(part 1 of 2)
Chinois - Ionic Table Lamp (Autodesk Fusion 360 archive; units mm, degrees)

design "Marble Base - Ionic Table Lamp - 120V" references "2-Pole Plug End", "Trove - TL", "Marble Base - Plastic Insert", "Balon v2", "Chinois", "Marble Base - Silicone Gasket", "Rubber Grommet", "Neoprene Pad", "T9 - Bulb", "T9-5In", "Arca Tall", "Facet Petite"
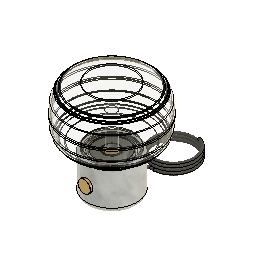
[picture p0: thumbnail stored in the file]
sketch "Sketch1" plane through (0, 0, 0) normal (0, 0, 1) x axis (1, 0, 0)
  circle C1 centre (0, 0) radius 63.5
  point P1 (0, 0)
  point P2 (0, 0)
  coincident P1 P2
extrude "Extrude1" new body sketch "Sketch1" along normal blind 101.6 bodies "Marble Base"
sketch "Sketch2" plane through (0, 0, 101.6) normal (0, 0, 1) x axis (-1, 0, 0)
  circle C1 centre (0, 0) radius 63.5
  circle C2 centre (0, 0) radius 53.975
  concentric C1 C2
  dimension "d3" diameter C2 = 107.95
extrude "Extrude2" cut sketch "Sketch2" profile of C2 against normal blind 34.925
sketch "Sketch3" plane through (0, 0, 66.675) normal (0, 0, 1) x axis (-1, 0, 0)
  circle C1 centre (0, 0) radius 53.975
  circle C2 centre (0, 0) radius 49.276
  point P1 (0, 0)
  point P3 (0, 0)
  coincident P1 P3
  dimension "d6" diameter C2 = 98.552
extrude "Extrude3" cut sketch "Sketch3" profile of C2 against normal blind 45.72
sketch "Sketch4" plane through (0, 0, 0) normal (0, 1, 0) x axis (1, 0, 0)
  circle C1 centre (0, -50.8) radius 3.81
  dimension "d9" diameter C1 = 7.62
extrude "Extrude4" cut sketch "Sketch4" against normal blind 127
sketch "Sketch5" plane through (0, 0, 0) normal (0, 1, 0) x axis (1, 0, 0)
  line L1 (0, -25.4) -> (0, 0)
  line L2 (0, -30.48) -> (0, -25.4)
  circle C1 centre (0, -30.48) radius 5.08
  point P1 (0, 0)
  point P2 (0, 0)
  point P4 (0, -30.48)
  point P5 (0, -30.48)
  coincident P1 P2
  vertical L1
  parallel L1 L2
  coincident P4 P5
  dimension "d12" diameter C1 = 10.16
extrude "Extrude5" cut sketch "Sketch5" profile of C1 along normal blind 114.3
fillet "Fillet1" radius 6.35 3.175 4.064
derived_base_feature "Derived Base Feature1" bodies "Rotary Switch"
derived_base_feature "Derived Base Feature1" bodies "Coiled - SVT (Blk Fabric)"
derived_base_feature "Derived Base Feature1" bodies "Glass Globe"
derived_base_feature "Derived Base Feature1" bodies "Metal Housing"
derived_base_feature "Derived Base Feature1" bodies "Metal Socket Cover"
derived_base_feature "Derived Base Feature1" bodies "Porcelain Socket"
derived_base_feature "Derived Base Feature1" bodies "Brass Dial - Dimmer Knob"
component_from_bodies "Body->Comp1"
offset_faces "OffsetFaces1" distance 12.7
offset_faces "OffsetFaces2" distance -12.7
derived_base_feature "Derived Base Feature1" bodies "Solitaire Petite"
move "Move1"
offset_faces "OffsetFaces1" distance 20.32
move "Move2"
extrude "Extrude6" add of existing geometry blind 25.4
offset_faces "OffsetFaces2" distance -3.81
fillet "Fillet2" radius 2.54
move "Move3"
derived_base_feature "Derived Base Feature2" bodies "Facet Petite"
move "Move4"
offset_faces "OffsetFaces1" distance 2.54
move "Move1"
derived_base_feature "Derived Base Feature1" bodies "Body1"
derived_base_feature "Derived Base Feature1" bodies "Body1"
derived_base_feature "Derived Base Feature1" bodies "Body1"
derived_base_feature "Derived Base Feature1" bodies "Body1"
derived_base_feature "Derived Base Feature1" bodies "Body1"
derived_base_feature "Derived Base Feature1" bodies "Body1", "Body2"
derived_base_feature "Derived Base Feature1" bodies "Body1"
position "Position1"
external_derived "ExternalDerived5" bodies "Plastic Insert"
derived_instance "DerivedInstance15"
offset_faces "OffsetFaces1" distance 3.81
offset_faces "OffsetFaces2" distance -1.0414
move "Move6"
external_derived "ExternalDerived6" sketch "Sketch3" bodies "Silicone Gasket"
derived_instance "DerivedInstance16"
offset_faces "OffsetFaces3" distance -10.795
move "Move1"
move_face "MoveFace1"
position "Position2"
position "Position3"
position "Position4"
position "Position5"
move "Move2"
position "Position6"
offset_faces "OffsetFaces2" distance -7.62
chamfer "Chamfer1" distance 0.381
remove_instance "RemoveInstance1"
remove_instance "RemoveInstance2"
remove_instance "RemoveInstance3"
remove_instance "RemoveInstance4"
move "Move1"
derived_base_feature "Derived Base Feature5" bodies "Oculo Petite"
align "Align1"
external_derived "ExternalDerived8"
derived_base_feature "Derived Base Feature7" bodies "Balon v2"
derived_base_feature "Derived Base Feature8" bodies "Balon v3"
align "Align3"
align "Align4"
external_derived "ExternalDerived10"
component_insert "Component Insert1"
position "Position7"
position "Position8"
derived_base_feature "Derived Base Feature11" bodies "Trove - TL"
move "Move10"
move "Move11"
remove_instance "RemoveInstance5"
split "Split1" bodies "Trove - TL (1)"
remove_body "RemoveBody2"
remove_body "RemoveBody3"
external_derived "ExternalDerived13" bodies "Trove - TL"
derived_instance "DerivedInstance20"
remove_body "RemoveBody4"
remove_body "RemoveBody5"
component_insert "Component Insert2"
component_insert "Component Insert3"
component_from_bodies "Body->Comp2"
remove_body "RemoveBody7"
move "Move12"
move "Move13"
sketch "Sketch6" plane through (0, 0, 97.917) normal (0, 0, 1) x axis (-1, 0, 0)
  circle C1 centre (0, 0) radius 41.275
  circle C2 centre (0, 0) radius 19.685
  arc A1 centre (0, 0) radius 29.3982 clockwise from (-27.6283, 10.0466) to (27.6283, 10.0466)
  arc A2 centre (0, 0) radius 26.2232 clockwise from (-24.6444, 8.9616) to (24.6444, 8.9616)
  arc A3 centre (0, 0) radius 32.5732 clockwise from (-30.6121, 11.1317) to (30.6121, 11.1317)
  arc A4 centre (0, 0) radius 35.7482 clockwise from (-33.596, 12.2167) to (33.596, 12.2167)
  point P1 (0, 0)
  point P3 (0, 0)
  coincident P1 P3
  dimension "d37" = -3.175
  dimension "d38" = 3.175
  dimension "d39" = 6.35
  dimension "d40" Text1-Height = 2.54
  dimension "d41" Text2-Height = 2.54
  dimension "d42" Text3-Height = 2.54
  dimension "d43" Text4-Height = 2.54
extrude "Extrude1" cut sketch "Sketch6" against normal blind 0.254
external_derived "ExternalDerived14" bodies "Rubber Grommet"
derived_instance "DerivedInstance19"
external_derived "ExternalDerived15" bodies "2-Pole Plug End"
derived_instance "DerivedInstance18"
external_derived "ExternalDerived16" bodies "Neoprene Pad"
derived_instance "DerivedInstance17"
position "Position9"
position "Position10"
position "Position11"
position "Position12"
external_derived "ExternalDerived17" bodies "Chinois"
derived_instance "DerivedInstance21"
position "Position13"
move "Move3"
remove_body "RemoveBody8"
component_insert "Component Insert4"
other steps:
derived_base_feature "Derived Base Feature1" bodies "Trove - TL"
derived_base_feature "Derived Base Feature1" bodies "Chinois"
derived_base_feature "Derived Base Feature1" bodies "Rubber Grommet"
derived_base_feature "Derived Base Feature1" bodies "2-Pole Plug End"
derived_base_feature "Derived Base Feature1" bodies "Neoprene Pad"
move "Move1"
base_feature "Base Feature1" bodies "Oculo Petite"
derived_base_feature "Derived Base Feature1" bodies "Plastic Insert"
derived_base_feature "Derived Base Feature1" bodies "Silicone Gasket"
base_feature "Base Feature1" bodies "Marble Base"
move "Move8"
derived_base_feature "Derived Base Feature"
create_component "CreateComponent1"
create_component "CreateComponent2"
create_component "CreateComponent3"
create_component "CreateComponent4"
create_component "CreateComponent5"
create_component "CreateComponent6"
create_component "CreateComponent7"
create_component "CreateComponent8"
remove_body "RemoveBody1"
create_component "CreateComponent9"
create_component "CreateComponent10"
create_component "CreateComponent11"
create_component "CreateComponent12"
create_component "CreateComponent13"
create_component "CreateComponent14"
create_component "CreateComponent15"
create_component "CreateComponent16"
create_component "CreateComponent17"
create_component "CreateComponent18"
remove_body "RemoveBody6"
create_component "CreateComponent19"
create_component "CreateComponent20"
create_component "CreateComponent21"
create_component "CreateComponent22"
create_component "CreateComponent23"
named bodies: "Marble Base", "Rotary Switch", "Coiled - SVT (Blk Fabric)", "Glass Globe", "Metal Housing", "Metal Socket Cover", "Porcelain Socket", "Brass Dial - Dimmer Knob", "Solitaire Petite", "Facet Petite", "Body1", "Body2", "Plastic Insert", "Silicone Gasket", "Oculo Petite", "Balon v2", "Balon v3", "Trove - TL", "Trove - TL (1)", "Neoprene Pad", "2-Pole Plug End", "Rubber Grommet", "Chinois"

design "Neoprene Pad"
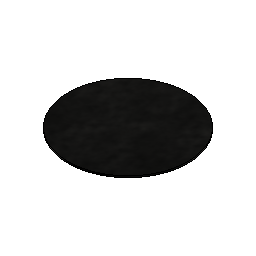
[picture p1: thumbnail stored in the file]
sketch "Sketch1" plane through (0, 0, 0) normal (0, 0, 1) x axis (1, 0, 0)
  circle C1 centre (0, 0) radius 57.15
  point P1 (0, 0)
  point P2 (0, 0)
  coincident P1 P2
extrude "Extrude1" new body sketch "Sketch1" along normal blind 1.5875 bodies "Neoprene Pad"
component_from_bodies "Body->Comp"
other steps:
base_feature "Base Feature" bodies "Neoprene Pad"
create_component "CreateComponent1"
remove_body "RemoveBody1"
named bodies: "Neoprene Pad"

design "T9 - Bulb"
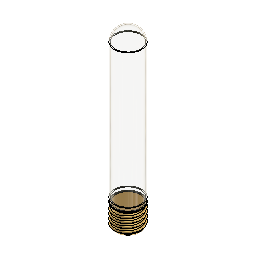
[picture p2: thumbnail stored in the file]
sketch "Sketch1" plane through (0, 0, 0) normal (0, 1, 0) x axis (1, 0, 0)
  line L1 (0, -166.37) -> (0, 0)
  line L2 (13.97, -13.97) -> (13.97, -152.4)
  line L3 (-13.97, -152.4) -> (-13.97, -13.97)
  line L4 (0, 0) -> (0, -166.37)
  line L5 (12.97, -13.97) -> (12.97, -152.4)
  line L6 (-12.97, -152.4) -> (-12.97, -13.97)
  line L7 (-12.3978, -10.16) -> (-13.4404, -10.16)
  line L8 (13.4404, -10.16) -> (12.3978, -10.16)
  arc A1 centre (0, -152.4) radius 13.97 clockwise from (13.97, -152.4) to (-13.97, -152.4)
  arc A2 centre (0, -152.4) radius 12.97 clockwise from (12.97, -152.4) to (-12.97, -152.4)
  arc A3 centre (0, -13.97) radius 13.97 clockwise from (13.4404, -10.16) to (13.97, -13.97)
  arc A4 centre (0, -13.97) radius 13.97 clockwise from (-13.97, -13.97) to (-13.4404, -10.16)
  arc A5 centre (0, -13.97) radius 12.97 clockwise from (12.3978, -10.16) to (12.97, -13.97)
  arc A6 centre (0, -13.97) radius 12.97 clockwise from (-12.97, -13.97) to (-12.3978, -10.16)
  point P1 (0, 0)
  point P2 (0, 0)
  point P3 (0, -166.37)
  point P10 (0, 0)
  point P17 (13.4404, -10.16)
  point P19 (12.3978, -10.16)
  point P4 (13.97, -152.4)
  point P5 (13.97, -13.97)
  coincident P1 P2
  vertical L1
  tangent L2 A3
  tangent L3 A3
  parallel L2 L3
  tangent L3 A1
  tangent L2 A1
  midpoint P3 A1
  coincident P1 P10
  perpendicular L1 L7
  coincident P17 L7
  concentric A3 A4
  coincident P10 A3
  concentric A1 A2
  tangent L5 A2
  tangent L5 A5
  tangent L6 A5
  tangent L6 A2
  coincident P19 L7
  concentric A5 A6
  collinear L7 L8
  dimension "d6" distance L2 L3 = 27.94
  dimension "d7" distance P4 P5 = 138.43
revolve "Revolve1" sketch "Sketch1" AlongAngle 360 bodies "T9"
derived_base_feature "Derived Base Feature" bodies "E26 Base"
align "Align1"
move "Move1"
component_from_bodies "Body->Comp1"
component_from_bodies "Body->Comp2"
copy_paste "CutPaste1"
copy_paste "CutPaste2"
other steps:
base_feature "Base Feature1" bodies "T9"
base_feature "Base Feature1" bodies "E26 Base"
create_component "CreateComponent1"
create_component "CreateComponent2"
remove_body "RemoveBody1"
create_component "CreateComponent3"
remove_body "RemoveBody2"
remove_instance "RemoveInstance1"
remove_instance "RemoveInstance2"
named bodies: "T9", "E26 Base"

design "Marble Base - Silicone Gasket"
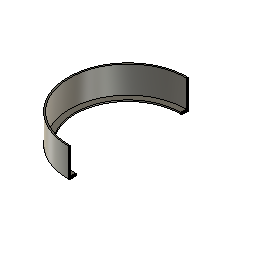
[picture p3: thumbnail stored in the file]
sketch "Sketch1" plane through (0, 0, 0) normal (0, 0, 1) x axis (1, 0, 0)
  circle C1 centre (0, 0) radius 53.34
  point P1 (0, 0)
  point P2 (0, 0)
  coincident P1 P2
extrude "Extrude1" new body sketch "Sketch1" along normal blind 25.4 bodies "Silicone Gasket"
shell "Shell1" innerThickness 1.27
sketch "Sketch2" plane through (0, 0, 1.27) normal (0, 0, 1) x axis (-1, 0, 0)
  circle C1 centre (0, 0) radius 52.07
  circle C2 centre (0, 0) radius 46.99
  concentric C1 C2
extrude "Extrude2" cut sketch "Sketch2" profile of C2 against normal blind 12.7
component_from_bodies "Body->Comp"
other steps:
base_feature "Base Feature" bodies "Silicone Gasket"
create_component "CreateComponent1"
remove_body "RemoveBody1"
named bodies: "Silicone Gasket"

design "2-Pole Plug End"
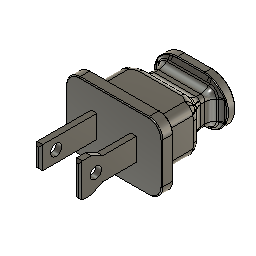
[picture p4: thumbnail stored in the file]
sketch "Sketch1" plane through (0, 0, 0) normal (0, 1, 0) x axis (1, 0, 0)
  line L1 (9.6837, 9.525) -> (-9.6837, 9.525)
  line L2 (13.4938, -5.715) -> (13.4938, 5.715)
  line L3 (-9.6837, -9.525) -> (9.6837, -9.525)
  line L4 (-13.4937, 5.715) -> (-13.4937, -5.715)
  line L5 (13.4938, -9.525) -> (-13.4937, 9.525)
  line L6 (-13.4937, -9.525) -> (13.4938, 9.525)
  arc A1 centre (-9.6837, -5.715) radius 3.81 clockwise from (-9.6837, -9.525) to (-13.4937, -5.715)
  arc A2 centre (9.6837, -5.715) radius 3.81 clockwise from (13.4938, -5.715) to (9.6837, -9.525)
  arc A3 centre (9.6837, 5.715) radius 3.81 clockwise from (9.6837, 9.525) to (13.4938, 5.715)
  arc A4 centre (-9.6837, 5.715) radius 3.81 clockwise from (-13.4937, 5.715) to (-9.6837, 9.525)
  point P6 (0, 0)
  point P1 (0, 0)
  point P5 (-13.4937, -9.525)
  point P4 (13.4938, -9.525)
  point P3 (13.4938, 9.525)
  point P2 (-13.4937, 9.525)
  horizontal L1
  perpendicular L1 L2
  parallel L1 L3
  parallel L2 L4
  coincident L5 P6
  coincident L6 P6
  coincident P1 P6
  coincident P5 L4
  coincident P5 L3
  tangent L4 A1
  tangent L3 A1
  coincident P4 L3
  coincident P4 L2
  tangent L3 A2
  tangent L2 A2
  equal A1 A2
  coincident P3 L2
  coincident P3 L1
  tangent L2 A3
  tangent L1 A3
  equal A1 A3
  coincident P2 L1
  coincident P2 L4
  tangent L1 A4
  tangent L4 A4
  equal A1 A4
  dimension "d1" distance P4 P5 = 26.9875
  dimension "d2" distance P2 P5 = 19.05
  dimension "d3" radius A1 = 3.81
extrude "Extrude1" new body sketch "Sketch1" profile of L1 L2 L3 L4 A1 A2 A3 A4 along normal blind 3.175
sketch "Sketch2" plane through (0, 3.175, 0) normal (0, 1, 0) x axis (-1, 0, 0)
  line L1 (9.6837, -9.525) -> (-9.6837, -9.525)
  line L2 (13.4937, 5.715) -> (13.4937, -5.715)
  line L3 (-9.6837, 9.525) -> (9.6837, 9.525)
  line L4 (-13.4938, -5.715) -> (-13.4938, 5.715)
  line L5 (10.16, -6.35) -> (-10.16, -6.35)
  line L6 (10.16, 6.35) -> (10.16, -6.35)
  line L7 (-10.16, 6.35) -> (10.16, 6.35)
  line L8 (-10.16, -6.35) -> (-10.16, 6.35)
  line L9 (10.16, 6.35) -> (-10.16, -6.35)
  line L10 (-10.16, 6.35) -> (10.16, -6.35)
  arc A1 centre (-9.6837, -5.715) radius 3.81 clockwise from (-9.6837, -9.525) to (-13.4938, -5.715)
  arc A2 centre (9.6837, -5.715) radius 3.81 clockwise from (13.4937, -5.715) to (9.6837, -9.525)
  arc A3 centre (9.6837, 5.715) radius 3.81 clockwise from (9.6837, 9.525) to (13.4937, 5.715)
  arc A4 centre (-9.6837, 5.715) radius 3.81 clockwise from (-13.4938, 5.715) to (-9.6837, 9.525)
  point P18 (0, 0)
  point P1 (0, 0)
  horizontal L5
  perpendicular L5 L6
  parallel L5 L7
  parallel L6 L8
  coincident L9 P18
  coincident L10 P18
  coincident P1 P18
extrude "Extrude2" add sketch "Sketch2" profile of L5 L6 L7 L8 along normal blind 9.525
sketch "Sketch3" plane through (0, 12.7, 0) normal (0, 1, 0) x axis (-1, 0, 0)
  line L1 (-10.16, -6.35) -> (-10.16, 6.35)
  line L2 (10.16, -6.35) -> (-10.16, -6.35)
  line L3 (10.16, 6.35) -> (10.16, -6.35)
  line L4 (-10.16, 6.35) -> (10.16, 6.35)
  line L5 (-7.1437, 3.9688) -> (7.1437, 3.9688)
  line L6 (-7.1437, -3.9688) -> (-7.1437, 3.9688)
  line L7 (7.1437, -3.9688) -> (-7.1437, -3.9688)
  line L8 (7.1437, 3.9688) -> (7.1437, -3.9688)
  line L9 (-7.1437, -3.9688) -> (7.1437, 3.9688)
  line L10 (7.1437, -3.9688) -> (-7.1437, 3.9688)
  point P10 (0, 0)
  point P1 (0, 0)
  point P8 (-7.1437, -3.9688)
  point P9 (7.1437, -3.9688)
  point P7 (-7.1437, 3.9688)
  horizontal L5
  perpendicular L5 L6
  parallel L5 L7
  parallel L6 L8
  coincident L9 P10
  coincident L10 P10
  coincident P1 P10
  dimension "d8" distance P8 P9 = 14.2875
  dimension "d9" distance P7 P8 = 7.9375
extrude "Extrude3" add sketch "Sketch3" profile of L5 L6 L7 L8 along normal blind 11.1125
fillet "Fillet1" radius 2.286 1.27 0.254
chamfer "Chamfer1" distance 3.429
fillet "Fillet2" radius 2.54 1.905
sketch "Sketch4" plane through (0, 23.8125, 0) normal (0, 1, 0) x axis (-1, 0, 0)
  line L1 (-7.1437, -2.6987) -> (-7.1437, 2.6987)
  line L2 (5.8737, -3.9688) -> (-5.8737, -3.9688)
  line L3 (7.1437, 2.6987) -> (7.1437, -2.6987)
  line L4 (-5.8737, 3.9688) -> (5.8737, 3.9688)
  line L5 (-3.81, 6.604) -> (3.81, 6.604)
  line L6 (3.81, -6.604) -> (-3.81, -6.604)
  line L7 (-10.414, 0) -> (10.414, 0)
  arc A1 centre (-5.8737, 2.6987) radius 1.27 clockwise from (-7.1437, 2.6987) to (-5.8737, 3.9688)
  arc A2 centre (-5.8737, -2.6987) radius 1.27 clockwise from (-5.8737, -3.9688) to (-7.1437, -2.6987)
  arc A3 centre (5.8737, -2.6987) radius 1.27 clockwise from (7.1437, -2.6987) to (5.8737, -3.9688)
  arc A4 centre (5.8737, 2.6987) radius 1.27 clockwise from (5.8737, 3.9688) to (7.1437, 2.6987)
  arc A5 centre (-3.81, 0) radius 6.604 clockwise from (-3.81, -6.604) to (-3.81, 6.604)
  arc A6 centre (3.81, 0) radius 6.604 clockwise from (3.81, 6.604) to (3.81, -6.604)
  point P20 (10.414, 0)
  point P21 (-10.414, 0)
  tangent L5 A5
  tangent A5 L6
  parallel L5 L6
  tangent L6 A6
  tangent L5 A6
  midpoint A6 P20
  midpoint A5 P21
  perpendicular L1 L7
extrude "Extrude4" add sketch "Sketch4" profile of A1 L1 A2 L2 A3 L3 A4 L4 L5 A5 L6 A6 against normal blind 2.286
chamfer "Chamfer2" distance 1.778
fillet "Fillet3" radius 1.778
fillet "Fillet4" radius 0.254
fillet "Fillet5" radius 0.254
fillet "Fillet6" radius 0.254
fillet "Fillet7" radius 3.175
sketch "Sketch5" plane through (0, 0, 0) normal (0, -1, 0) x axis (1, 0, 0)
  line L1 (-13.2397, -5.715) -> (-13.2397, 5.715)
  line L2 (9.6837, -9.271) -> (-9.6837, -9.271)
  line L3 (13.2397, 5.715) -> (13.2397, -5.715)
  line L4 (-9.6837, 9.271) -> (9.6837, 9.271)
  line L5 (-6.35, -3.175) -> (-6.35, 3.175)
  line L6 (6.35, 3.175) -> (-6.35, -3.175)
  line L7 (-6.35, 3.175) -> (6.35, -3.175)
  line L8 (-4.7625, 3.175) -> (-6.35, 3.175)
  line L9 (-4.7625, -3.175) -> (-4.7625, 3.175)
  line L10 (-6.35, -3.175) -> (-4.7625, -3.175)
  line L11 (-6.35, 3.175) -> (-6.35, -3.175)
  line L12 (0, -3.302) -> (0, 3.81)
  line L13 (4.7625, -3.175) -> (4.7625, 3.175)
  line L14 (4.7625, 3.175) -> (6.35, 3.175)
  line L15 (6.35, -3.175) -> (6.35, 3.175)
  line L16 (6.35, -3.175) -> (4.7625, -3.175)
  arc A1 centre (-9.6837, 5.715) radius 3.556 clockwise from (-13.2397, 5.715) to (-9.6837, 9.271)
  arc A2 centre (-9.6837, -5.715) radius 3.556 clockwise from (-9.6837, -9.271) to (-13.2397, -5.715)
  arc A3 centre (9.6837, -5.715) radius 3.556 clockwise from (13.2397, -5.715) to (9.6837, -9.271)
  arc A4 centre (9.6837, 5.715) radius 3.556 clockwise from (9.6837, 9.271) to (13.2397, 5.715)
  point P18 (0, 0)
  point P1 (0, 0)
  point P14 (-6.35, -3.175)
  point P27 (6.35, -3.175)
  point P17 (-6.35, 3.175)
  point P26 (6.35, 3.175)
  point P19 (-4.7625, 3.175)
  point P24 (4.7625, 3.175)
  point P20 (-4.7625, -3.175)
  point P25 (4.7625, -3.175)
  point P21 (-6.35, -3.175)
  point P28 (6.35, -3.175)
  point P15 (6.35, -3.175)
  point P16 (6.35, 3.175)
  coincident L6 P18
  coincident L7 P18
  coincident P1 P18
  horizontal L8
  vertical L9
  horizontal L10
  vertical L11
  vertical L12
  symmetric P14 L12 P27
  symmetric P17 L12 P26
  symmetric P19 L12 P24
  symmetric P20 L12 P25
  symmetric P21 L12 P28
  dimension "d36" distance P15 P16 = 6.35
  dimension "d37" distance P17 P19 = 1.5875
extrude "Extrude5" add sketch "Sketch5" profile of L5 L8 L9 L10 L11 L13 L14 L15 L16 along normal blind 15.875
sketch "Sketch7" plane through (0, 0, 3.175) normal (0, 0, 1) x axis (-1, 0, 0)
  line L1 (-4.7625, 0) -> (-6.35, 0)
  line L2 (-4.7625, 15.875) -> (-4.7625, 0)
  line L3 (-6.35, 15.875) -> (-4.7625, 15.875)
  line L4 (-6.35, 0) -> (-6.35, 15.875)
  line L5 (-4.7625, 15.875) -> (-6.35, 15.875)
  line L6 (-4.7625, 9.525) -> (-4.7625, 15.875)
  line L7 (-6.35, 9.525) -> (-4.7625, 9.525)
  line L8 (-6.35, 15.875) -> (-6.35, 9.525)
  point P5 (-6.35, 15.875)
  point P6 (-6.35, 15.875)
  point P9 (-6.35, 9.525)
  horizontal L5
  vertical L6
  horizontal L7
  vertical L8
  coincident P5 P6
  dimension "d45" distance P6 P9 = 6.35
extrude "Extrude7" add sketch "Sketch7" profile of L2 L3 L4 L5 L6 L7 L8 against normal blind 7.9375 and along normal blind 1.5875
chamfer "Chamfer3" distance 0.508
chamfer "Chamfer4" distance 0.635 distance 0.635
sketch "Sketch6" plane through (6.35, 0, 0) normal (1, 0, 0) x axis (0, 1, 0)
  line L1 (0, -3.175) -> (-9.525, -3.175)
  line L2 (0, 3.175) -> (0, -3.175)
  line L3 (-9.525, 3.175) -> (0, 3.175)
  line L4 (-15.367, -4.6355) -> (-15.367, 4.6355)
  line L5 (-11.43, 0) -> (-16.002, 0)
  line L6 (-9.525, -4.7625) -> (-15.24, -4.7625)
  line L7 (-9.525, -3.175) -> (-9.525, -4.7625)
  line L8 (-9.525, 4.7625) -> (-9.525, 3.175)
  line L9 (-15.24, 4.7625) -> (-9.525, 4.7625)
  line L10 (-15.24, -4.7625) -> (-15.367, -4.6355)
  line L11 (-15.367, 4.6355) -> (-15.24, 4.7625)
  circle C1 centre (-11.43, 0) radius 1.5875
  point P9 (-11.43, 0)
  point P10 (-11.43, 0)
  perpendicular L4 L5
  coincident P9 P10
  dimension "d42" diameter C1 = 3.175
extrude "Extrude6" cut sketch "Sketch6" profile of C1 against normal blind 20.32
chamfer "Chamfer5" distance 3.175 distance 1.5875 distance 3.175 distance 1.5875
component_from_bodies "Body->Comp"
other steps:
base_feature "Base Feature" bodies "2-Pole Plug End"
create_component "CreateComponent1"
remove_body "RemoveBody1"
named bodies: "2-Pole Plug End"

design "Facet Petite"
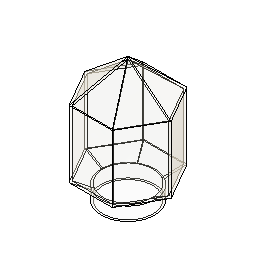
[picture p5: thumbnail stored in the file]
sketch "Sketch7" plane through (0, 0, 0) normal (1, 0, 0) x axis (0, 1, 0)
sketch "Sketch8" plane through (0, 0, 0) normal (0, 0, 1) x axis (1, 0, 0)
  circle C1 centre (0, 0) radius 50.8
  point P1 (0, 0)
  point P2 (0, 0)
  coincident P1 P2
  dimension "d17" diameter C1 = 101.6
extrude "Extrude5" new body sketch "Sketch8" along normal blind 25.4 and against normal blind 25.4
work_plane "WorkPlane1" AlongDistance 17.78
sketch "Sketch10" plane through (0, 0, 25.4) normal (0, 0, 1) x axis (-1, 0, 0)
  circle C1 centre (0, 0) radius 50.8
sketch "Sketch12" plane through (0, 0, 43.18) normal (0, 0, 1) x axis (1, 0, 0)
  line L1 (-82.1223, 0) -> (-41.0612, 71.12)
  line L2 (-41.0612, -71.12) -> (-82.1223, 0)
  line L3 (41.0612, -71.12) -> (-41.0612, -71.12)
  line L4 (82.1223, 0) -> (41.0612, -71.12)
  line L5 (41.0612, 71.12) -> (82.1223, 0)
  line L6 (-41.0612, 71.12) -> (41.0612, 71.12)
  point P1 (0, 0)
  point P8 (0, 0)
  coincident P1 P8
  dimension "d22" distance P8 L6 = 71.12
sketch "Sketch15" plane through (0, 0, 0) normal (0, 1, 0) x axis (1, 0, 0)
  line L1 (53.7365, -21.6801) -> (82.1223, -43.18)
  line L2 (-50.8, -25.4) -> (-82.1223, -43.18)
  point P2 (82.1223, -43.18)
  point P3 (82.1223, -43.18)
  point P5 (-82.1223, -43.18)
  point P7 (-82.1223, -43.18)
  point P6 (-50.8, -25.4)
  point P8 (-50.8, -25.4)
  coincident P2 P3
  coincident P5 P7
  coincident P6 P8
sketch "Sketch17" plane through (0, 0, 25.4) normal (0, 0, 1) x axis (-1, 0, 0)
  line L1 (51.3255, 0) -> (0, 0)
  line L2 (73.3235, 0) -> (0, 0)
  line L3 (-41.0612, -71.12) -> (-25.4, -43.9941)
  line L4 (-36.6617, -63.5) -> (-25.4, -43.9941)
  line L5 (78.4305, 0) -> (0, 0)
  line L6 (41.0612, -71.12) -> (25.4, -43.9941)
  line L7 (25.4, 43.9941) -> (41.0612, 71.12)
  line L8 (73.3235, 0) -> (0, 0)
  line L9 (-25.4, 43.9941) -> (-41.0612, 71.12)
  line L10 (0, 0) -> (0, 0)
  circle C1 centre (0, 0) radius 50.8
  point P1 (0, 0)
  point P4 (0, 0)
  point P2 (-41.0612, -71.12)
  point P6 (-41.0612, -71.12)
  point P3 (0, 0)
  point P7 (0, 0)
  point P9 (-25.4, -43.9941)
  point P12 (41.0612, -71.12)
  point P13 (41.0612, -71.12)
  point P15 (25.4, -43.9941)
  point P16 (41.0612, 71.12)
  point P17 (41.0612, 71.12)
  point P18 (25.4, 43.9941)
  point P19 (-41.0612, 71.12)
  point P20 (-41.0612, 71.12)
  point P21 (0, 0)
  point P23 (-25.4, 43.9941)
  point P25 (0, 0)
  point P24 (0, 0)
  point P26 (0, 0)
  horizontal L1
  coincident P1 P4
  coincident P2 P6
  horizontal L2
  coincident P3 P7
  coincident C1 P9
  coincident P12 P13
  horizontal L5
  coincident C1 P15
  coincident P16 P17
  coincident C1 P18
  coincident P19 P20
  horizontal L8
  coincident P1 P21
  coincident C1 P23
  coincident P1 P25
  coincident P24 P26
extrude "Extrude6" new body sketch "Sketch12" along normal blind 127
work_plane "WorkPlane2" AlongDistance 66.04
sketch "Sketch18" plane through (0, 0, 236.22) normal (0, 0, 1) x axis (1, 0, 0)
  line L1 (41.0612, -71.12) -> (0, 0)
  line L2 (82.1223, 0) -> (0, 0)
  line L3 (41.0612, 71.12) -> (0, 0)
  line L4 (-41.0612, 71.12) -> (0, 0)
  line L5 (-82.1223, 0) -> (0, 0)
  line L6 (-41.0612, -71.12) -> (0, 0)
  point P1 (0, 0)
  point P3 (0, 0)
  point P2 (41.0612, -71.12)
  point P4 (41.0612, -71.12)
  point P6 (0, 0)
  point P5 (82.1223, 0)
  point P7 (82.1223, 0)
  point P9 (0, 0)
  point P8 (41.0612, 71.12)
  point P10 (41.0612, 71.12)
  point P12 (0, 0)
  point P11 (-41.0612, 71.12)
  point P13 (-41.0612, 71.12)
  point P15 (0, 0)
  point P14 (-82.1223, 0)
  point P16 (-82.1223, 0)
  point P18 (0, 0)
  point P17 (-41.0612, -71.12)
  point P19 (-41.0612, -71.12)
  coincident P1 P3
  coincident P2 P4
  coincident P1 P6
  coincident P5 P7
  coincident P1 P9
  coincident P8 P10
  coincident P1 P12
  coincident P11 P13
  coincident P1 P15
  coincident P14 P16
  coincident P1 P18
  coincident P17 P19
loft "Loft1"
loft "Loft2" sketch "Sketch17"
component_from_bodies "Body->Comp"
extrude "Extrude1" cut of existing geometry blind -25.4
shell "Shell2" innerThickness 3.81
fillet "Fillet1" radius 7.62
fillet "Fillet2" radius 6.35
fillet "Fillet3" radius 6.35
fillet "Fillet4" radius 6.35
fillet "Fillet5" radius 6.35
fillet "Fillet6" radius 6.35
fillet "Fillet7" radius 3.81
fillet "Fillet8" radius 6.35
fillet "Fillet9" radius 6.35
fillet "Fillet10" radius 6.35
fillet "Fillet11" radius 6.35
fillet "Fillet12" radius 6.35
fillet "Fillet13" radius 2.286
shell "Shell1" innerThickness 2.54
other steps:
base_feature "Base Feature"
create_component "CreateComponent3"
remove_body "RemoveBody2"

design "Chinois"
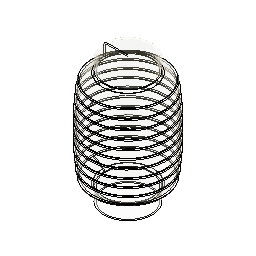
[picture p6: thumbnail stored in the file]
named bodies: "Chinois"

design "Marble Base - Plastic Insert"
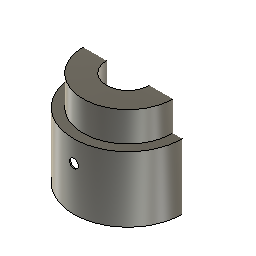
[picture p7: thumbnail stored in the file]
sketch "Sketch1" plane through (0, 0, 0) normal (0, 0, 1) x axis (1, 0, 0)
  circle C1 centre (0, 0) radius 50.038
  point P1 (0, 0)
  point P2 (0, 0)
  coincident P1 P2
  dimension "d1" diameter C1 = 100.076
extrude "Extrude1" new body sketch "Sketch1" along normal blind 72.898 bodies "Plastic Insert"
shell "Shell1" innerThickness 1.016
work_plane "WorkPlane1" AlongDistance 18.034
sketch "Sketch2" plane through (0, 0, 90.932) normal (0, 0, 1) x axis (1, 0, 0)
  circle C1 centre (0, 0) radius 20.701
  point P1 (0, 0)
  point P2 (0, 0)
  coincident P1 P2
  dimension "d6" diameter C1 = 41.402
extrude "Extrude2" add sketch "Sketch2" against normal blind 65.024
shell "Shell2" innerThickness 1.016
sketch "Sketch3" plane through (0, 0, 0) normal (0, 1, 0) x axis (1, 0, 0)
  line L1 (5.08, -20.32) -> (-5.08, -20.32)
  line L2 (5.08, 20.32) -> (5.08, -20.32)
  line L3 (-5.08, 20.32) -> (5.08, 20.32)
  line L4 (-5.08, -20.32) -> (-5.08, 20.32)
  line L5 (5.08, 20.32) -> (-5.08, -20.32)
  line L6 (-5.08, 20.32) -> (5.08, -20.32)
  point P6 (0, 0)
  point P1 (0, 0)
  horizontal L1
  perpendicular L1 L2
  parallel L1 L3
  parallel L2 L4
  coincident L5 P6
  coincident L6 P6
  coincident P1 P6
extrude "Extrude3" cut sketch "Sketch3" profile of L1 L2 L3 L4 along normal blind 91.44
sketch "Sketch4" plane through (0, 0, 0) normal (0, 1, 0) x axis (1, 0, 0)
  line L1 (0, -40.64) -> (0, 0)
  circle C1 centre (0, -40.64) radius 4.064
  point P1 (0, 0)
  point P2 (0, 0)
  point P3 (0, -40.64)
  point P4 (0, -40.64)
  coincident P1 P2
  vertical L1
  coincident P3 P4
  dimension "d12" diameter C1 = 8.128
work_plane "WorkPlane2" AlongDistance -91.44
sketch "Sketch5" plane through (0, -91.44, 0) normal (0, 1, 0) x axis (1, 0, 0)
  circle C1 centre (0, -40.64) radius 4.064
extrude "Extrude4" cut sketch "Sketch5" along normal blind 63.5
sketch "Sketch6" plane through (0, 0, 26.924) normal (0, 0, 1) x axis (-1, 0, 0)
  circle C1 centre (0, 0) radius 19.685
  circle C2 centre (0, 0) radius 5.461
  concentric C1 C2
  dimension "d16" diameter C2 = 10.922
extrude "Extrude5" cut sketch "Sketch6" profile of C2 against normal blind 15.24
sketch "Sketch7" plane through (0, 0, 72.898) normal (0, 0, 1) x axis (-1, 0, 0)
  circle C1 centre (0, 0) radius 20.701
  circle C2 centre (0, 0) radius 50.038
  circle C3 centre (0, 0) radius 20.701
  circle C4 centre (0, 0) radius 45.72
  point P1 (0, 0)
  point P3 (0, 0)
  point P4 (0, 0)
  coincident P1 P3
  coincident P1 P4
extrude "Extrude6" add sketch "Sketch7" profile of C1 C3 C4 along normal blind 18.034
sketch "Sketch8" plane through (0, 0, 71.882) normal (0, 0, -1) x axis (1, 0, 0)
  circle C1 centre (0, 0) radius 20.701
  circle C2 centre (0, 0) radius 49.022
  circle C3 centre (0, 0) radius 20.701
  circle C4 centre (0, 0) radius 44.704
  point P1 (0, 0)
  point P3 (0, 0)
  point P4 (0, 0)
  coincident P1 P3
  coincident P1 P4
  dimension "d21" diameter C4 = 89.408
extrude "Extrude7" cut sketch "Sketch8" profile of C1 C3 C4 against normal blind 17.78
extrude "Extrude8" add of existing geometry blind 9.398
extrude "Extrude9" cut of existing geometry blind -9.398
component_from_bodies "Body->Comp"
offset_faces "OffsetFaces1" distance 4.445
offset_faces "OffsetFaces2" distance -4.445
offset_faces "OffsetFaces3" distance 3.175
offset_faces "OffsetFaces4" distance 3.175
offset_faces "OffsetFaces5" distance 3.175
offset_faces "OffsetFaces6" distance -3.175
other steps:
base_feature "Base Feature" bodies "Plastic Insert"
create_component "CreateComponent1"
remove_body "RemoveBody1"
named bodies: "Plastic Insert"

design "Arca Tall"
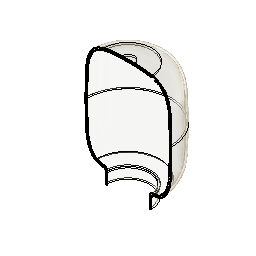
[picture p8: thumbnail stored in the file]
derived_base_feature "Derived Base Feature" bodies "Balon"
work_plane "WorkPlane1" AlongDistance 0
sketch "Sketch1" plane through (0, 0, 0) normal (0, 1, 0) x axis (1, 0, 0)
  line L1 (0, 317.5) -> (0, 2.9083)
  curve K1 (-82.9821, 124.2212) -> (-50.8, 237.8015)
  curve K2 (-51.0925, 237.681) -> (-50.8, 237.8015)
  curve K3 (-51.3855, 237.5558) -> (-51.0925, 237.681)
  curve K4 (-54.7608, 236.0513) -> (-51.3855, 237.5558)
  curve K5 (-57.9615, 234.05) -> (-54.7608, 236.0513)
  curve K6 (-67.2727, 226.749) -> (-57.9615, 234.05)
  curve K7 (-69.0552, 224.2615) -> (-67.2727, 226.749)
  curve K8 (-72.1872, 218.7832) -> (-69.0552, 224.2615)
  curve K9 (-74.1213, 215.1556) -> (-72.1872, 218.7832)
  curve K10 (-78.3031, 204.3965) -> (-74.1213, 215.1556)
  curve K11 (-79.7275, 197.3397) -> (-78.3031, 204.3965)
  curve K12 (-81.3333, 185.4664) -> (-79.7275, 197.3397)
  curve K13 (-81.6254, 178.4008) -> (-81.3333, 185.4664)
  curve K14 (-82.49, 152.2133) -> (-81.6254, 178.4008)
  curve K15 (-82.9821, 136.067) -> (-82.49, 152.2133)
  curve K16 (-82.9821, 124.2212) -> (-82.9821, 136.067)
  curve K17 (50.8, 237.7999) -> (82.9821, 124.2212)
  curve K18 (82.9821, 140.3031) -> (82.9821, 124.2212)
  curve K19 (81.9353, 169.4257) -> (82.9821, 140.3031)
  curve K20 (81.3621, 183.6489) -> (81.9353, 169.4257)
  curve K21 (80.9478, 189.8724) -> (81.3621, 183.6489)
  curve K22 (77.8147, 206.9858) -> (80.9478, 189.8724)
  curve K23 (74.9652, 213.2153) -> (77.8147, 206.9858)
  curve K24 (69.4688, 224.1531) -> (74.9652, 213.2153)
  curve K25 (67.2512, 226.458) -> (69.4688, 224.1531)
  curve K26 (61.5696, 231.3138) -> (67.2512, 226.458)
  curve K27 (57.377, 234.6711) -> (61.5696, 231.3138)
  curve K28 (52.0556, 237.2628) -> (57.377, 234.6711)
  curve K29 (51.4313, 237.5413) -> (52.0556, 237.2628)
  curve K30 (50.8, 237.7999) -> (51.4313, 237.5413)
  line L2 (-50.8, 317.5) -> (-50.8, 237.8015)
  line L3 (50.8, 317.5) -> (50.8, 237.7999)
  line L4 (-19.0713, 6.7501) -> (-19.0713, 6.7501)
  curve K31 (82.9821, 124.1958) -> (40.1509, 7.3012)
  curve K32 (41.8198, 7.6176) -> (40.1509, 7.3012)
  curve K33 (43.2113, 8.0663) -> (41.8198, 7.6176)
  curve K34 (47.0139, 9.2854) -> (43.2113, 8.0663)
  curve K35 (47.3314, 9.3805) -> (47.0139, 9.2854)
  curve K36 (50.1192, 10.3272) -> (47.3314, 9.3805)
  curve K37 (51.833, 11.0085) -> (50.1192, 10.3272)
  curve K38 (57.8313, 14.1895) -> (51.833, 11.0085)
  curve K39 (61.4491, 17.0488) -> (57.8313, 14.1895)
  curve K40 (66.8203, 21.5867) -> (61.4491, 17.0488)
  curve K41 (68.5372, 23.5528) -> (66.8203, 21.5867)
  curve K42 (71.2201, 27.8971) -> (68.5372, 23.5528)
  curve K43 (74.7424, 33.8984) -> (71.2201, 27.8971)
  curve K44 (78.2342, 44.8406) -> (74.7424, 33.8984)
  curve K45 (79.6792, 50.3463) -> (78.2342, 44.8406)
  curve K46 (81.3558, 63.5576) -> (79.6792, 50.3463)
  curve K47 (81.6386, 70.4415) -> (81.3558, 63.5576)
  curve K48 (82.4897, 96.2198) -> (81.6386, 70.4415)
  curve K49 (82.9814, 112.3523) -> (82.4897, 96.2198)
  curve K50 (82.9821, 124.1958) -> (82.9814, 112.3523)
  curve K51 (-40.1501, 7.301) -> (-82.9821, 124.1958)
  curve K52 (-82.9813, 110.5256) -> (-82.9821, 124.1958)
  curve K53 (-82.2545, 88.8594) -> (-82.9813, 110.5256)
  curve K54 (-81.6277, 70.519) -> (-82.2545, 88.8594)
  curve K55 (-81.3572, 64.3441) -> (-81.6277, 70.519)
  curve K56 (-79.4149, 46.8924) -> (-81.3572, 64.3441)
  curve K57 (-76.5204, 38.9768) -> (-79.4149, 46.8924)
  curve K58 (-73.5142, 32.2947) -> (-76.5204, 38.9768)
  curve K59 (-72.5556, 30.3818) -> (-73.5142, 32.2947)
  curve K60 (-69.7914, 25.3691) -> (-72.5556, 30.3818)
  curve K61 (-68.3824, 23.4028) -> (-69.7914, 25.3691)
  curve K62 (-64.5419, 19.5456) -> (-68.3824, 23.4028)
  curve K63 (-62.3002, 17.7646) -> (-64.5419, 19.5456)
  curve K64 (-53.6583, 11.1976) -> (-62.3002, 17.7646)
  curve K65 (-49.6968, 10.1396) -> (-53.6583, 11.1976)
  curve K66 (-43.4141, 8.1331) -> (-49.6968, 10.1396)
  curve K67 (-41.9704, 7.6516) -> (-43.4141, 8.1331)
  curve K68 (-40.1963, 7.3098) -> (-41.9704, 7.6516)
  curve K69 (-40.1732, 7.3054) -> (-40.1963, 7.3098)
  curve K70 (-40.1501, 7.301) -> (-40.1732, 7.3054)
  line L5 (-82.9821, 124.1958) -> (-82.9821, 124.2212)
  line L6 (82.9821, 124.2212) -> (82.9821, 124.1958)
  line L7 (0, 317.5) -> (-50.8, 317.5)
  line L8 (7.2015, 3.048) -> (0, 3.048)
  line L9 (0, 3.048) -> (-7.2015, 3.048)
  arc A1 centre (0, 188.595) radius 185.6867 clockwise from (-7.2015, 3.048) to (-40.1502, 7.301)
  arc A2 centre (0, 188.595) radius 185.6867 clockwise from (40.151, 7.3012) to (7.2015, 3.048)
  point P38 (-40.1502, 7.301)
  point P43 (40.1509, 7.3012)
  point P62 (-40.1501, 7.301)
  point P81 (40.151, 7.3012)
  point P84 (0, 3.048)
  vertical L1
  horizontal L4
  coincident P38 K51
  symmetric L1 A1 A2
  coincident A2 P43
  coincident A1 P62
  coincident K31 P81
  perpendicular L2 L7
  horizontal L8
  coincident L1 P84
  horizontal L9
revolve "Revolve1" sketch "Sketch1" AlongAngle 360
shell "Shell1" innerThickness 3.81
fillet "Fillet1" radius 6.35 bodies "Balon v3"
offset_faces "OffsetFaces1" distance -50.8
move "Move1"
move "Move2"
component_from_bodies "Body->Comp1"
component_from_bodies "Body->Comp2"
sketch "Sketch2" plane through (0, 0, 0) normal (0, 1, 0) x axis (1, 0, 0)
  line L1 (-85.5221, 124.2212) -> (-85.5221, 124.1961)
  curve K1 (-58.9057, 236.4383) -> (-50.8, 241.7989)
  curve K2 (-50.8, 241.554) -> (-50.8, 241.7989)
  curve K3 (-50.904, 240.933) -> (-50.8, 241.554)
  curve K4 (-51.2936, 240.2837) -> (-50.904, 240.933)
  curve K5 (-51.734, 239.7561) -> (-51.2936, 240.2837)
  curve K6 (-53.328, 238.5038) -> (-51.734, 239.7561)
  curve K7 (-54.0892, 238.1997) -> (-53.328, 238.5038)
  curve K8 (-58.9057, 236.4383) -> (-54.0892, 238.1997)
  curve K9 (-89.3309, 124.2212) -> (-58.9057, 236.4383)
  curve K10 (-62.6336, 234.9735) -> (-58.9057, 236.4383)
  curve K11 (-65.581, 233.1032) -> (-62.6336, 234.9735)
  curve K12 (-73.0224, 227.0019) -> (-65.581, 233.1032)
  curve K13 (-74.8981, 224.836) -> (-73.0224, 227.0019)
  curve K14 (-78.1104, 219.6097) -> (-74.8981, 224.836)
  curve K15 (-80.2663, 215.561) -> (-78.1104, 219.6097)
  curve K16 (-84.0943, 205.8277) -> (-80.2663, 215.561)
  curve K17 (-85.4655, 200.1154) -> (-84.0943, 205.8277)
  curve K18 (-87.4092, 188.5789) -> (-85.4655, 200.1154)
  curve K19 (-87.7349, 182.3889) -> (-87.4092, 188.5789)
  curve K20 (-88.4233, 165.9645) -> (-87.7349, 182.3889)
  curve K21 (-89.328, 138.6964) -> (-88.4233, 165.9645)
  curve K22 (-89.3309, 124.2212) -> (-89.328, 138.6964)
  line L2 (-89.3309, 124.1958) -> (-89.3309, 124.2212)
  curve K23 (-46.5001, 7.301) -> (-89.3309, 124.1958)
  curve K24 (-89.3314, 112.4293) -> (-89.3309, 124.1958)
  curve K25 (-88.8181, 95.3068) -> (-89.3314, 112.4293)
  curve K26 (-88.346, 81.2892) -> (-88.8181, 95.3068)
  curve K27 (-88.0298, 70.4902) -> (-88.346, 81.2892)
  curve K28 (-87.1514, 58.328) -> (-88.0298, 70.4902)
  curve K29 (-86.3326, 50.6119) -> (-87.1514, 58.328)
  curve K30 (-81.0932, 33.6688) -> (-86.3326, 50.6119)
  curve K31 (-77.3163, 27.4309) -> (-81.0932, 33.6688)
  curve K32 (-74.8955, 23.6666) -> (-77.3163, 27.4309)
  curve K33 (-73.5108, 22.0741) -> (-74.8955, 23.6666)
  curve K34 (-70.2346, 19.0457) -> (-73.5108, 22.0741)
  curve K35 (-64.8094, 14.3548) -> (-70.2346, 19.0457)
  curve K36 (-56.6696, 10.3041) -> (-64.8094, 14.3548)
  curve K37 (-54.0053, 9.483) -> (-56.6696, 10.3041)
  curve K38 (-49.1487, 7.9411) -> (-54.0053, 9.483)
  curve K39 (-48.3482, 7.6526) -> (-49.1487, 7.9411)
  curve K40 (-46.5001, 7.301) -> (-48.3482, 7.6526)
  line L3 (0, 266.7) -> (0, 0)
  line L4 (0, 3.048) -> (-7.7894, 3.048)
  line L5 (-50.8, 266.7) -> (-50.8, 241.7989)
  line L6 (0, 266.7) -> (-50.8, 266.7)
  arc A1 centre (-6.9779, 188.7329) radius 185.6867 clockwise from (-7.7894, 3.048) to (-46.5001, 7.301)
  point P1 (0, 0)
  point P44 (0, 0)
  point P46 (0, 3.048)
  point P5 (-50.8, 241.554)
  point P49 (0, 266.7)
  coincident P1 P44
  coincident L3 P46
  coincident P5 L5
  coincident L3 P49
revolve "Revolve2" sketch "Sketch2" AlongAngle 360 bodies "Balon v3"
shell "Shell2" innerThickness 3.81
component_from_bodies "Body->Comp3"
remove_instance "RemoveInstance1"
remove_instance "RemoveInstance2"
sketch "Sketch1" plane through (0, 0, 0) normal (0, 1, 0) x axis (1, 0, 0)
  line L1 (-6.35, 3.048) -> (-14.1394, 3.048)
  curve K1 (-52.8501, 7.301) -> (-95.6809, 124.1958)
  curve K2 (-95.6814, 112.4293) -> (-95.6809, 124.1958)
  curve K3 (-95.1681, 95.3068) -> (-95.6814, 112.4293)
  curve K4 (-94.696, 81.2892) -> (-95.1681, 95.3068)
  curve K5 (-94.3798, 70.4902) -> (-94.696, 81.2892)
  curve K6 (-93.5014, 58.328) -> (-94.3798, 70.4902)
  curve K7 (-92.6826, 50.6119) -> (-93.5014, 58.328)
  curve K8 (-87.4432, 33.6688) -> (-92.6826, 50.6119)
  curve K9 (-83.6663, 27.4309) -> (-87.4432, 33.6688)
  curve K10 (-81.2455, 23.6666) -> (-83.6663, 27.4309)
  curve K11 (-79.8608, 22.0741) -> (-81.2455, 23.6666)
  curve K12 (-76.5846, 19.0457) -> (-79.8608, 22.0741)
  curve K13 (-71.12, 13.97) -> (-76.5846, 19.0457)
  curve K14 (-62.23, 10.16) -> (-71.12, 13.97)
  curve K15 (-60.3553, 9.483) -> (-62.23, 10.16)
  curve K16 (-55.4987, 7.9411) -> (-60.3553, 9.483)
  curve K17 (-54.6982, 7.6526) -> (-55.4987, 7.9411)
  curve K18 (-52.8501, 7.301) -> (-54.6982, 7.6526)
  line L2 (-95.6809, 124.1958) -> (-95.6809, 124.2212)
  line L3 (0, 266.7) -> (0, 0)
  line L4 (0, 3.048) -> (-6.35, 3.048)
  line L5 (-95.6809, 124.2466) -> (-95.6809, 124.2212)
  line L6 (-50.8, 266.7) -> (-50.8, 241.7989)
  line L7 (0, 266.7) -> (-50.8, 266.7)
  curve K19 (-71.6837, 232.5587) -> (-50.8, 241.7989)
  curve K20 (-50.8, 237.8015) -> (-50.8, 241.7989)
  curve K21 (-53.6019, 236.5654) -> (-50.8, 237.8015)
  curve K22 (-59.7861, 236.0598) -> (-53.6019, 236.5654)
  curve K23 (-64.4375, 235.2772) -> (-59.7861, 236.0598)
  curve K24 (-69.8917, 233.4707) -> (-64.4375, 235.2772)
  curve K25 (-71.6837, 232.5587) -> (-69.8917, 233.4707)
  curve K26 (-71.6837, 232.5587) -> (-95.6809, 124.2466)
  curve K27 (-95.6814, 136.0132) -> (-95.6809, 124.2466)
  curve K28 (-95.1681, 153.1357) -> (-95.6814, 136.0132)
  curve K29 (-94.696, 167.1533) -> (-95.1681, 153.1357)
  curve K30 (-94.3798, 177.9523) -> (-94.696, 167.1533)
  curve K31 (-93.5014, 190.1145) -> (-94.3798, 177.9523)
  curve K32 (-92.6826, 197.8306) -> (-93.5014, 190.1145)
  curve K33 (-87.4432, 214.7737) -> (-92.6826, 197.8306)
  curve K34 (-83.6663, 221.0115) -> (-87.4432, 214.7737)
  curve K35 (-81.2455, 224.7759) -> (-83.6663, 221.0115)
  curve K36 (-79.8608, 226.3684) -> (-81.2455, 224.7759)
  curve K37 (-77.083, 228.9361) -> (-79.8608, 226.3684)
  curve K38 (-75.5537, 230.2778) -> (-77.083, 228.9361)
  curve K39 (-71.6837, 232.5587) -> (-75.5537, 230.2778)
  curve K40 (-50.8, 244.8458) -> (-50.8, 244.8469)
  curve K41 (-50.8, 244.8465) -> (-50.8, 244.8469)
  curve K42 (-50.8, 244.8462) -> (-50.8, 244.8465)
  curve K43 (-50.8, 244.8458) -> (-50.8, 244.8462)
  arc A1 centre (-13.3279, 188.7329) radius 185.6867 clockwise from (-14.1394, 3.048) to (-52.8501, 7.301)
  point P26 (0, 3.048)
  point P33 (-50.8, 237.8015)
  point P35 (-50.8, 237.8015)
  point P40 (-71.6837, 232.5587)
  point P53 (-50.8, 244.8458)
  coincident L3 P26
  perpendicular L3 L4
  coincident P33 P35
  coincident K19 P40
  coincident L6 P53
sketch "Sketch2" plane through (0, 0, 0) normal (0, 1, 0) x axis (1, 0, 0)
  line L1 (-95.6809, 124.1958) -> (-95.6809, 124.2212)
  line L2 (0, 266.7) -> (-50.8, 266.7)
  curve K1 (-58.9317, 239.3909) -> (-50.8, 244.8469)
  curve K2 (-50.8, 244.602) -> (-50.8, 244.8469)
  curve K3 (-50.904, 243.981) -> (-50.8, 244.602)
  curve K4 (-51.2936, 243.3317) -> (-50.904, 243.981)
  curve K5 (-51.734, 242.8041) -> (-51.2936, 243.3317)
  curve K6 (-53.328, 241.5518) -> (-51.734, 242.8041)
  curve K7 (-54.0892, 241.2477) -> (-53.328, 241.5518)
  curve K8 (-58.9317, 239.3909) -> (-54.0892, 241.2477)
  line L3 (-50.8, 266.7) -> (-50.8, 244.8458)
  curve K9 (-52.8501, 7.301) -> (-95.6809, 124.1958)
  curve K10 (-95.6814, 112.4293) -> (-95.6809, 124.1958)
  curve K11 (-95.1681, 95.3068) -> (-95.6814, 112.4293)
  curve K12 (-94.696, 81.2892) -> (-95.1681, 95.3068)
  curve K13 (-94.3798, 70.4902) -> (-94.696, 81.2892)
  curve K14 (-93.5014, 58.328) -> (-94.3798, 70.4902)
  curve K15 (-92.6826, 50.6119) -> (-93.5014, 58.328)
  curve K16 (-87.4432, 33.6688) -> (-92.6826, 50.6119)
  curve K17 (-83.6663, 27.4309) -> (-87.4432, 33.6688)
  curve K18 (-81.2455, 23.6666) -> (-83.6663, 27.4309)
  curve K19 (-79.8608, 22.0741) -> (-81.2455, 23.6666)
  curve K20 (-76.5846, 19.0457) -> (-79.8608, 22.0741)
  curve K21 (-73.7599, 16.6033) -> (-76.5846, 19.0457)
  curve K22 (-65.532, 11.7145) -> (-73.7599, 16.6033)
  curve K23 (-60.3553, 9.483) -> (-65.532, 11.7145)
  curve K24 (-55.4987, 7.9411) -> (-60.3553, 9.483)
  curve K25 (-54.6982, 7.6526) -> (-55.4987, 7.9411)
  curve K26 (-52.8501, 7.301) -> (-54.6982, 7.6526)
  line L4 (-95.6809, 124.2466) -> (-95.6809, 124.2212)
  line L5 (0, 3.048) -> (-6.35, 3.048)
  line L6 (-6.35, 3.048) -> (-14.1394, 3.048)
  curve K27 (-58.9317, 239.3909) -> (-95.6809, 124.2466)
  curve K28 (-95.6814, 136.0132) -> (-95.6809, 124.2466)
  curve K29 (-95.1681, 153.1357) -> (-95.6814, 136.0132)
  curve K30 (-94.696, 167.1533) -> (-95.1681, 153.1357)
  curve K31 (-94.3798, 177.9523) -> (-94.696, 167.1533)
  curve K32 (-93.5014, 190.1145) -> (-94.3798, 177.9523)
  curve K33 (-92.6826, 197.8306) -> (-93.5014, 190.1145)
  curve K34 (-87.4432, 214.7737) -> (-92.6826, 197.8306)
  curve K35 (-83.6663, 221.0115) -> (-87.4432, 214.7737)
  curve K36 (-81.2455, 224.7759) -> (-83.6663, 221.0115)
  curve K37 (-79.8608, 226.3684) -> (-81.2455, 224.7759)
  curve K38 (-76.5846, 229.3968) -> (-79.8608, 226.3684)
  curve K39 (-73.7599, 231.8391) -> (-76.5846, 229.3968)
  curve K40 (-65.833, 236.5491) -> (-73.7599, 231.8391)
  curve K41 (-61.4585, 238.4785) -> (-65.833, 236.5491)
  curve K42 (-58.9317, 239.3909) -> (-61.4585, 238.4785)
  line L7 (0, 3.048) -> (0, 266.7)
  arc A1 centre (-13.3279, 188.7329) radius 185.6867 clockwise from (-14.1394, 3.048) to (-52.8501, 7.301)
  point P52 (-50.8, 244.8458)
  coincident K1 P52
  perpendicular L5 L7
revolve "Revolve1" sketch "Sketch1" AlongAngle 360 bodies "Balon v3.3"
shell "Shell1" innerThickness 3.81
revolve "Revolve2" sketch "Sketch2" AlongAngle 360 bodies "Balon v3.2"
shell "Shell2" innerThickness 3.81
component_from_bodies "Body->Comp1"
component_from_bodies "Body->Comp2"
position "Position1"
remove_instance "RemoveInstance1" bodies "Balon v3"
remove_instance "RemoveInstance2"
move "Move1"
position "Position2" bodies "Balon v3"
sketch "Sketch3" plane through (0, 0, 0) normal (0, 1, 0) x axis (1, 0, 0)
  line L1 (0, 50.8) -> (0, -304.8)
  line L2 (127, 50.8) -> (127, -304.8)
  line L3 (-127, 50.8) -> (-127, -304.8)
  line L4 (139.7, 25.4) -> (-139.7, 25.4)
  line L5 (139.7, -292.1) -> (-139.7, -292.1)
  line L6 (95.25, 50.8) -> (95.25, -304.8)
  vertical L1
  dimension "d6" = 127
  dimension "d12" = -127
  dimension "d17" distance L4 L5 = 317.5
  dimension "d18" = 95.25
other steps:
base_feature "Base Feature1" bodies "Balon v3.3"
base_feature "Base Feature1" bodies "Balon v3.2"
base_feature "Base Feature1" bodies "Balon"
base_feature "Base Feature1" bodies "Balon v3"
base_feature "Base Feature1" bodies "Balon v2"
create_component "CreateComponent1"
remove_body "RemoveBody1"
create_component "CreateComponent2"
remove_body "RemoveBody2"
create_component "CreateComponent3"
remove_body "RemoveBody3" bodies "Balon v3"
create_component "CreateComponent1"
create_component "CreateComponent2"
remove_body "RemoveBody1" bodies "Balon v3"
create_component "CreateComponent3"
remove_body "RemoveBody2" bodies "Balon v3"
named bodies: "Balon", "Balon v2", "Balon v3", "Balon v3.3", "Balon v3.2"

design "Rubber Grommet"
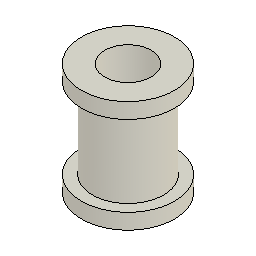
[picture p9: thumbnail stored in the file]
sketch "Sketch1" plane through (0, 0, 0) normal (0, 1, 0) x axis (1, 0, 0)
  line L1 (0, 3.048) -> (0, -12.7)
  line L2 (5.842, 0.508) -> (5.842, -12.7)
  line L3 (3.81, 3.048) -> (3.81, -15.24)
  line L4 (7.62, -12.7) -> (7.62, -15.24)
  line L5 (7.62, 3.048) -> (7.62, 0.508)
  line L6 (7.62, 0.508) -> (5.842, 0.508)
  line L7 (7.62, -12.7) -> (5.842, -12.7)
  line L8 (7.62, -15.24) -> (3.81, -15.24)
  line L9 (7.62, 3.048) -> (3.81, 3.048)
  vertical L1
  collinear L4 L5
revolve "Revolve1" sketch "Sketch1" AlongAngle 360 bodies "Rubber Grommet"
component_from_bodies "Body->Comp"
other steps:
base_feature "Base Feature" bodies "Rubber Grommet"
create_component "CreateComponent1"
remove_body "RemoveBody1"
named bodies: "Rubber Grommet"

design "Trove - TL"
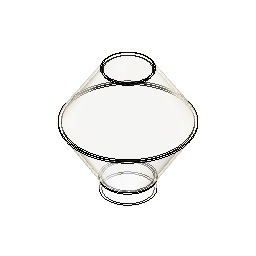
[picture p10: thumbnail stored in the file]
derived_base_feature "Derived Base Feature" bodies "Trove"
hole "Hole1" HoleDepth 88.9 HoleDiameter 44.45 TipAngle 118
sketch "Sketch1" plane through (0, 0, 0) normal (1, 0, 0) x axis (0, 1, 0)
  line L1 (0, 243.0601) -> (0, 247.8226)
  line L2 (-50.8, -12.7122) -> (-50.8, 10.9447)
  line L3 (0, -25.4) -> (0, 243.0601)
  line L4 (-46.0375, -12.7122) -> (-50.8, -12.7122)
  line L5 (-46.0375, -12.7122) -> (-46.0375, 12.3043)
  line L6 (-45.9716, 247.8226) -> (0, 247.8226)
  line L7 (-43.3841, 243.0601) -> (0, 243.0601)
  line L8 (-122.8321, 128.6352) -> (-51.757, 14.2971)
  line L9 (-117.1907, 128.5808) -> (-46.9945, 15.6567)
  line L10 (-48.6353, 246.3754) -> (-122.7993, 132.0392)
  line L11 (-46.0478, 241.6129) -> (-117.1579, 131.9848)
  arc A1 centre (-57.15, 10.9447) radius 6.35 clockwise from (-51.757, 14.2971) to (-50.8, 10.9447)
  arc A2 centre (-52.3875, 12.3043) radius 6.35 clockwise from (-46.9945, 15.6567) to (-46.0375, 12.3043)
  arc A3 centre (-114.4942, 130.257) radius 3.175 between (-117.1579, 131.9848) and (-117.1907, 128.5808)
  arc A4 centre (-120.1356, 130.3114) radius 3.175 between (-122.7993, 132.0392) and (-122.8321, 128.6352)
  arc A5 centre (-45.9716, 244.6476) radius 3.175 between (-45.9716, 247.8226) and (-48.6353, 246.3754)
  arc A6 centre (-43.3841, 239.8851) radius 3.175 clockwise from (-46.0478, 241.6129) to (-43.3841, 243.0601)
  point P3 (0, 247.8226)
  point P4 (0, 243.0601)
  vertical L1
  vertical L3
  tangent L5 A2
  perpendicular L1 L6
  perpendicular L1 L7
  tangent L11 A3
  tangent L9 A3
  tangent L10 A4
  tangent L8 A4
  equal A3 A4
  tangent L6 A5
  tangent L10 A5
  tangent L11 A6
  tangent L7 A6
  dimension "d8" distance P3 P4 = 4.7625
  dimension "d11" radius A2 = 6.35
  dimension "d15" radius A3 = 3.175
  dimension "d16" radius A5 = 3.175
  dimension "d17" radius A6 = 3.175
revolve "Revolve1" sketch "Sketch1" AlongAngle 180 bodies "Trove - TL"
revolve "Revolve2" sketch "Sketch1" AlongAngle -180
component_from_bodies "Body->Comp"
remove_body "RemoveBody2"
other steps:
base_feature "Base Feature" bodies "Trove - TL"
create_component "CreateComponent1"
remove_body "RemoveBody1"
named bodies: "Trove", "Trove - TL"

design "T9-5In"
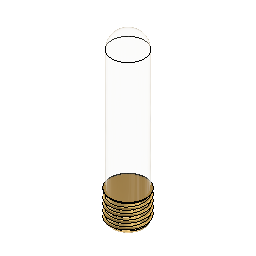
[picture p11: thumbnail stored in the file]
sketch "Sketch1" plane through (0, 0, 0) normal (0, 1, 0) x axis (1, 0, 0)
  line L1 (0, 0) -> (0, -127)
  line L2 (12.7, -127) -> (-12.7, -127)
  line L3 (12.7, -12.7) -> (12.7, -127)
  line L4 (-12.7, -127) -> (-12.7, -12.7)
  arc A1 centre (0, -12.7) radius 12.7 clockwise from (-12.7, -12.7) to (12.7, -12.7)
  point P1 (0, 0)
  point P3 (0, 0)
  coincident P1 P3
  vertical L1
  horizontal L2
  vertical L3
  vertical L4
revolve "Revolve1" sketch "Sketch1" AlongAngle 360 bodies "BU-T10-5-LED-120V"
derived_base_feature "Derived Base Feature" bodies "E26 Base"
move "Move1"
component_from_bodies "Body->Comp"
copy_paste "CutPaste"
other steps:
base_feature "Base Feature" bodies "BU-T10-5-LED-120V"
create_component "CreateComponent1"
create_component "CreateComponent2"
remove_body "RemoveBody1"
remove_instance "RemoveInstance1"
named bodies: "BU-T10-5-LED-120V", "E26 Base"

design "Balon v2"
